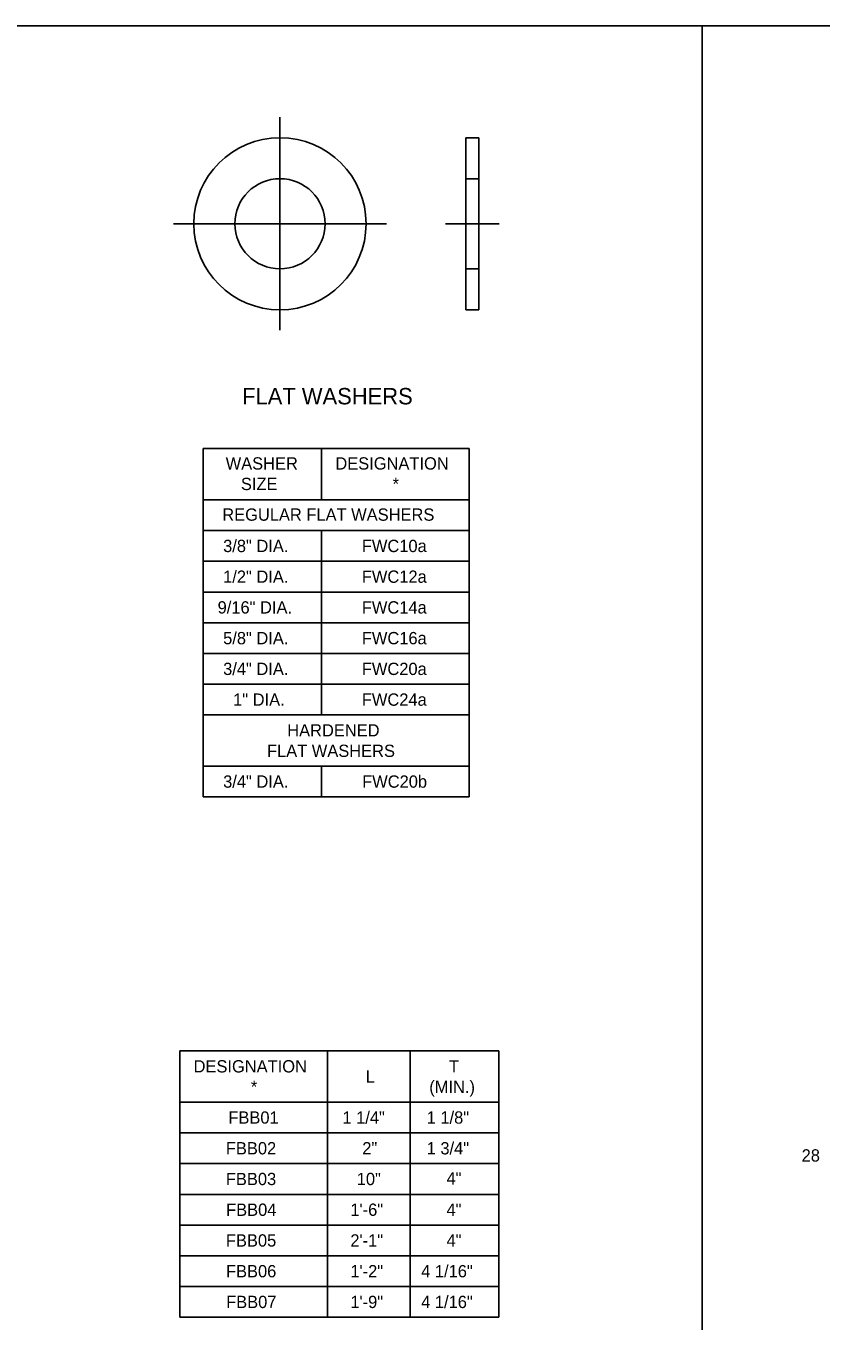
# Model space of a CAD drawing. Extents: x 49991.4 to 50021, y 49987.6 to 50011.4.
# Drawn here: x 50004.77 to 50008.65, y 49992.68 to 49999 of the extents above; entities that cross this region are included whole.
import ezdxf

# ---------------------------------------------------------------- set-up
doc = ezdxf.new("R2010")
doc.units = 0
for name, color, linetype in [('Level 1', 7, 'Continuous'), ('Level 2', 7, 'Continuous'), ('Level 4', 7, 'Continuous'), ('Level 5', 7, 'Continuous')]:
    doc.layers.add(name, color=color, linetype=linetype)

msp = doc.modelspace()

# ---------------------------------------------------------------- linework, layer by layer
at = {"layer": 'Level 1'}
for p, q in [((50008.0668, 49998.9992), (50008.0668, 49987.7988)), ((50006.9151, 49997.6135), (50006.9151, 49998.4535)), ((50006.9151, 49998.4535), (50006.9771, 49998.4535)), ((50006.9771, 49997.6135), (50006.9771, 49998.4535)), ((50006.9151, 49997.6135), (50006.9771, 49997.6135))]:
    msp.add_line(p, q, dxfattribs=at)
msp.add_lwpolyline([(49999.3835, 49998.9992), (50016.7501, 49998.9992), (50016.7501, 49987.7988), (49999.3835, 49987.7988)], close=True, dxfattribs=at)
for radius in [0.42, 0.22]:
    msp.add_circle((50006.008, 49998.0335), radius, dxfattribs=at)
at = {"layer": 'Level 2'}
for p, q in [((50005.6341, 49995.236), (50005.6341, 49996.936)), ((50005.6341, 49996.936), (50006.9308, 49996.936)), ((50006.2108, 49996.686), (50006.2108, 49996.936)), ((50006.9308, 49995.236), (50006.9308, 49996.936)), ((50005.6341, 49996.686), (50006.9308, 49996.686)), ((50005.6341, 49996.536), (50006.9308, 49996.536)), ((50006.2108, 49995.636), (50006.2108, 49996.536)), ((50005.6341, 49996.386), (50006.9308, 49996.386)), ((50005.6341, 49996.236), (50006.9308, 49996.236)), ((50005.6341, 49996.086), (50006.9308, 49996.086)), ((50005.6341, 49995.936), (50006.9308, 49995.936)), ((50005.6341, 49995.786), (50006.9308, 49995.786)), ((50005.6341, 49995.636), (50006.9308, 49995.636)), ((50005.6341, 49995.386), (50006.9308, 49995.386)), ((50006.2108, 49995.236), (50006.2108, 49995.386)), ((50005.6341, 49995.236), (50006.9308, 49995.236)), ((50005.5191, 49992.6961), (50005.5191, 49993.9961)), ((50005.5191, 49993.9961), (50007.0758, 49993.9961)), ((50006.2391, 49992.6961), (50006.2391, 49993.9961)), ((50006.6424, 49992.6961), (50006.6424, 49993.9961)), ((50007.0758, 49992.6961), (50007.0758, 49993.9961)), ((50005.5191, 49993.7461), (50007.0758, 49993.7461)), ((50005.5191, 49993.5961), (50007.0758, 49993.5961)), ((50005.5191, 49993.4461), (50007.0758, 49993.4461)), ((50005.5191, 49993.2961), (50007.0758, 49993.2961)), ((50005.5191, 49993.1461), (50007.0758, 49993.1461)), ((50005.5191, 49992.9961), (50007.0758, 49992.9961)), ((50005.5191, 49992.8461), (50007.0758, 49992.8461)), ((50005.5191, 49992.6961), (50007.0758, 49992.6961))]:
    msp.add_line(p, q, dxfattribs=at)
at = {"layer": 'Level 4'}
for p, q in [((50006.9151, 49998.2535), (50006.9771, 49998.2535)), ((50006.9151, 49997.8135), (50006.9771, 49997.8135))]:
    msp.add_line(p, q, dxfattribs=at)
at = {"layer": 'Level 5'}
for p, q in [((50006.008, 49997.5135), (50006.008, 49998.5535)), ((50006.528, 49998.0335), (50005.488, 49998.0335)), ((50006.8151, 49998.0335), (50007.0771, 49998.0335))]:
    msp.add_line(p, q, dxfattribs=at)

# ---------------------------------------------------------------- texts
at = {"layer": 'Level 2'}
for s, height, p in [('FLAT WASHERS', 0.08, (50005.8233, 49997.1519)), ('WASHER', 0.06, (50005.7431, 49996.8337)), ('DESIGNATION', 0.06, (50006.2781, 49996.8337)), ('SIZE', 0.06, (50005.8174, 49996.7337)), ('*', 0.06, (50006.5573, 49996.7337)), ('REGULAR FLAT WASHERS', 0.06, (50005.7266, 49996.584)), ('3/8" DIA.', 0.06, (50005.7308, 49996.431)), ('FWC10a', 0.06, (50006.4072, 49996.431)), ('1/2" DIA.', 0.06, (50005.7308, 49996.281)), ('FWC12a', 0.06, (50006.4072, 49996.281)), ('9/16" DIA.', 0.06, (50005.7038, 49996.131)), ('FWC14a', 0.06, (50006.4072, 49996.131)), ('5/8" DIA.', 0.06, (50005.7308, 49995.981)), ('FWC16a', 0.06, (50006.4072, 49995.981)), ('3/4" DIA.', 0.06, (50005.7308, 49995.831)), ('FWC20a', 0.06, (50006.4072, 49995.831)), ('1" DIA.', 0.06, (50005.7795, 49995.681)), ('FWC24a', 0.06, (50006.4072, 49995.681)), ('HARDENED', 0.06, (50006.0434, 49995.531)), ('FLAT WASHERS', 0.06, (50005.9447, 49995.431)), ('3/4" DIA.', 0.06, (50005.7308, 49995.281)), ('FWC20b', 0.06, (50006.4088, 49995.281)), ('DESIGNATION', 0.06, (50005.5866, 49993.8911)), ('T', 0.06, (50006.8322, 49993.8911)), ('L', 0.06, (50006.4262, 49993.8411)), ('*', 0.06, (50005.8659, 49993.7911)), ('(MIN.)', 0.06, (50006.7363, 49993.7911)), ('FBB01', 0.06, (50005.7563, 49993.6412)), ('1 1/4"', 0.06, (50006.3127, 49993.6412)), ('1 1/8"', 0.06, (50006.7235, 49993.6412)), ('FBB02', 0.06, (50005.7441, 49993.4912)), ('2"', 0.06, (50006.4094, 49993.4912)), ('1 3/4"', 0.06, (50006.7235, 49993.4912)), ('28', 0.06, (50008.5524, 49993.4563)), ('FBB03', 0.06, (50005.7441, 49993.3412)), ('10"', 0.06, (50006.3825, 49993.3412)), ('4"', 0.06, (50006.8202, 49993.3442)), ('FBB04', 0.06, (50005.7453, 49993.1912)), ('1\'-6"', 0.06, (50006.3513, 49993.1912)), ('4"', 0.06, (50006.8202, 49993.1912)), ('FBB05', 0.06, (50005.7444, 49993.0412)), ('2\'-1"', 0.06, (50006.3513, 49993.0412)), ('4"', 0.06, (50006.8203, 49993.0412)), ('FBB06', 0.06, (50005.7448, 49992.8912)), ('1\'-2"', 0.06, (50006.3513, 49992.8912)), ('4 1/16"', 0.06, (50006.6966, 49992.8912)), ('FBB07', 0.06, (50005.7455, 49992.7412)), ('1\'-9"', 0.06, (50006.3513, 49992.7412)), ('4 1/16"', 0.06, (50006.6966, 49992.7412))]:
    msp.add_text(s, height=height, dxfattribs=at).set_placement(p)

doc.saveas('drawing.dxf')
